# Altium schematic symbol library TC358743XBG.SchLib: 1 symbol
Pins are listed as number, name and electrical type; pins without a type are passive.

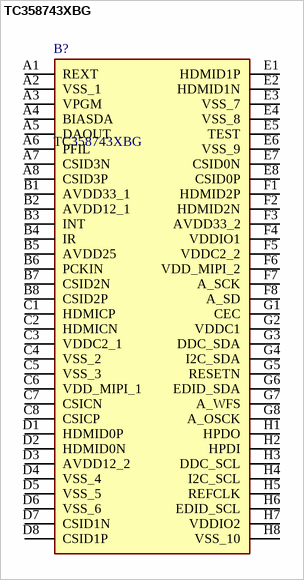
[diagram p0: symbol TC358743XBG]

## TC358743XBG
designator B?
Display Drivers & Controllers HDMI to CSI-2 bridge chip; Manufacturer_Name: Toshiba; Geometry.Height: 1.2mm
footprint BGA64C65P8X8_600X600X120
pins: A1 REXT, A2 VSS_1, A3 VPGM, A4 BIASDA, A5 DAOUT, A6 PFIL, A7 CSID3N, A8 CSID3P, B1 AVDD33_1, B2 AVDD12_1, B3 INT, B4 IR, B5 AVDD25, B6 PCKIN, B7 CSID2N, B8 CSID2P, C1 HDMICP, C2 HDMICN, C3 VDDC2_1, C4 VSS_2, C5 VSS_3, C6 VDD_MIPI_1, C7 CSICN, C8 CSICP, D1 HDMID0P, D2 HDMID0N, D3 AVDD12_2, D4 VSS_4, D5 VSS_5, D6 VSS_6, D7 CSID1N, D8 CSID1P, E1 HDMID1P, E2 HDMID1N, E3 VSS_7, E4 VSS_8, E5 TEST, E6 VSS_9, E7 CSID0N, E8 CSID0P, F1 HDMID2P, F2 HDMID2N, F3 AVDD33_2, F4 VDDIO1, F5 VDDC2_2, F6 VDD_MIPI_2, F7 A_SCK, F8 A_SD, G1 CEC, G2 VDDC1, G3 DDC_SDA, G4 I2C_SDA, G5 RESETN, G6 EDID_SDA, G7 A_WFS, G8 A_OSCK, H1 HPDO, H2 HPDI, H3 DDC_SCL, H4 I2C_SCL, H5 REFCLK, H6 EDID_SCL, H7 VDDIO2, H8 VSS_10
